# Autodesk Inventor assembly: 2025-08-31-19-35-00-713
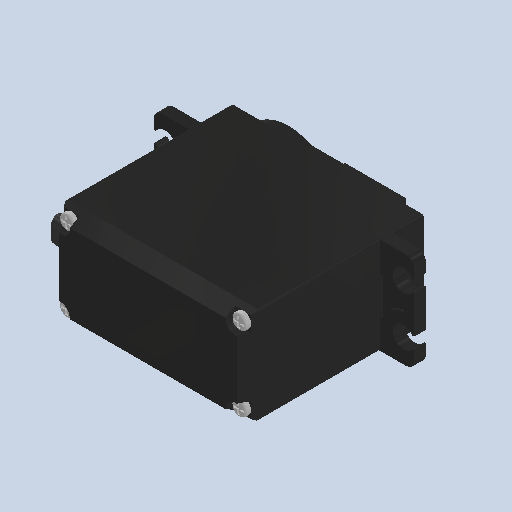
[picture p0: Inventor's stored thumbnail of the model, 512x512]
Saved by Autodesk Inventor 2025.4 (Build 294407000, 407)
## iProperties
Created: 2026-09
Part Number: 2025-08-31-19-35-00-713
Document SubType Name: Assembly
Designer: AdminForWorker
Title: MG995 v1
Author: AdminForWorker
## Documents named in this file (2)
- c:\worker\convert-fusion-r05-cosv3\tmp\job-1\19\temp\files\ca3d996b-dda0-445d-8bee-12a194174ca8\MG995 v1_2.iam
- c:\worker\convert-fusion-r05-cosv3\tmp\job-1\19\temp\files\ca3d996b-dda0-445d-8bee-12a194174ca8\Servo_2.iam
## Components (1 placed, 1 different names)
1. Servo:1 [sub-assembly]
